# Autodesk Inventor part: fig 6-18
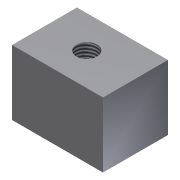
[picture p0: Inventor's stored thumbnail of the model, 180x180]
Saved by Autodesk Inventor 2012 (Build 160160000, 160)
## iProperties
Created: 2009-09
Part Number: fig 6-18
Document SubType Name: Modeling
Designer: Sham
Density: 1 g/cm^3
Material: Default
Author: Sham
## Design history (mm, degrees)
sketch "Sketch1"
  geometry: L1 (-28, 20)-(0, 20); L2 (0, 20)-(0, 0); L3 (0, 0)-(-28, 0); L4 (-28, 0)-(-28, 20)
  constraints: 8 end point, 2 parallel, 1 horizontal, 1 perpendicular
extrude "Extrusion1" new body sketch "Sketch1" distance "d0" = 20; taper "d1" = 0 deg
hole "Hole1" diameter "d4" = 5.944; stored, may be unused: countersink angle "d8" = 90 deg, drill point angle "d10" = 118 deg; dims "d2" = 10, "d3" = 15, "d5" = 5.946, "d6" = 12, "d7" = 3, "d9" = 15, "d11" = 0.62479, "d12" = 5.994
body "Solid1"
